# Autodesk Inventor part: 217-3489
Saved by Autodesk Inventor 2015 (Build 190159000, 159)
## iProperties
Created: 2014-11
Part Number: 217-3489
Material: Generic
Document SubType Name: Modeling
Designer: User
Density: 1 g/cm^3
Appearance: Default
Author: User
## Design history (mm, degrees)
node "217-3489.ipt1"
node "Chamfer1"
node "Base1"
